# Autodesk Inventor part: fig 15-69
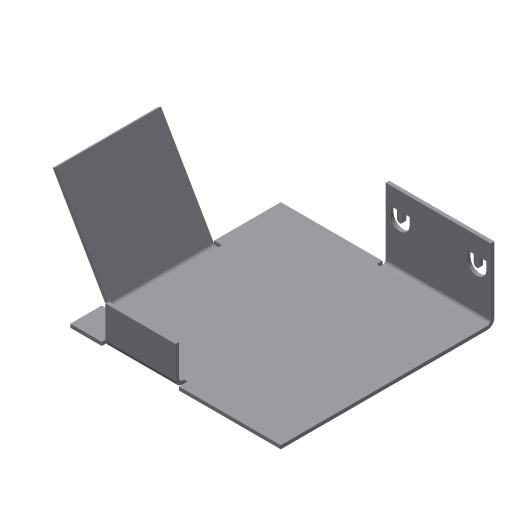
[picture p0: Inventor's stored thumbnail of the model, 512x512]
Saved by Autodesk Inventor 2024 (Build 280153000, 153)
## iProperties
Shininess: 77.0
Angle Display Precision: 2
Document Length Units: 11269
Document Angle Units: 11279
Document Time Units: 11290
Document Mass Units: 11283
Document Length Units Precision: 3
Document Angle Units Precision: 2
Created: 2002-04
Part Number: fig 15-69
Document SubType Name: Sheet Metal
Density: 1 g/cm^3
Sheet Metal Rule: Default
Material: Generic
Appearance: Default
Density: 0.0
Volumn: 0.0
Area: 0.0
PropertySet Name: Model Information
Control State: 0
Master: False
Checked Out: False
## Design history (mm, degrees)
node "Face1"
  sketch "Sketch1"
    geometry: L1 (12.647, 25.882)-(12.647, -14.118); L2 (12.647, -14.118)-(-17.353, -14.118); L3 (-17.353, -14.118)-(-17.353, 15.882); L4 (-17.353, 15.882)-(-2.353, 15.882); L5 (-2.353, 15.882)-(-2.353, 25.882); L6 (-2.353, 25.882)-(12.647, 25.882); 1 further point
    constraints: 12 end point, 4 parallel, 1 perpendicular
    dimensions: "d5" = 30 distance of L2.end L3.end; "d6" = 10 distance of L4.end L5.end; "d7" = 15 distance of L3.end L4.end; "d25" = 15 distance of L5.end L1.start
sketch "Sketch3"
  geometry: L1 (10, -15)-(10, 0)
  constraints: 2 end point
feature "Fold3" sketch "Sketch3" dims "d26" = 0.5 (= BendRadius), "d27" = 90 deg, "d28" = 0.5 (= BendRadius), "d96" = 0.5 (= BendReliefWidth), "d97" = 0.25 (= BendReliefDepth), "d98" = 1 (= MinimumRemnant), "d107" = 0.5 (= Thickness), "SeamGap" = 0.01
node "Flange2"
sketch "Sketch6"
  geometry: L1 (-6.914, 3.413)-(-5.843, 3.413); L2 (-5.843, 0.624)-(-6.914, 0.624); L3 (-6.914, 2.432)-(-5.843, 2.432); L4 (-5.843, 1.605)-(-6.914, 1.605); L5 (-6.914, 0.624)-(-6.914, 1.605); L6 (-6.914, 2.432)-(-6.914, 3.413); L7 (-6.914, 12.568)-(-6.914, 11.587); L8 (-6.914, 14.376)-(-6.914, 13.395); L9 (-6.914, 11.587)-(-5.843, 11.587); L10 (-5.843, 14.376)-(-6.914, 14.376); L11 (-6.914, 12.568)-(-5.843, 12.568); L12 (-5.843, 13.395)-(-6.914, 13.395); A1 r 1.394 centre (-5.843, 2.018) between (-5.843, 0.624) and (-5.843, 3.413); A2 r 0.413 centre (-5.843, 2.018) between (-5.843, 1.605) and (-5.843, 2.432); A3 r 1.394 centre (-5.843, 12.982) between (-5.843, 11.587) and (-5.843, 14.376); A4 r 0.413 centre (-5.843, 12.982) between (-5.843, 12.568) and (-5.843, 13.395)
  constraints: 24 end point, 8 point on circle, 4 centre point, 3 equal length, 1 perpendicular
cut "Cut1" sketch "Sketch6" dims "d49" = 0.5 (= Thickness), "d50" = 0
node "Flange3"
body "Solid1"
face "Plate1" dims "d107" = 0.5 (= Thickness)
sketch "Sketch5"
  geometry: L1 (20, 0)-(5, 0); L2 (5, 0)-(5, 15); L3 (5, 15)-(20, 15); L4 (20, 15)-(20, 0)
  constraints: 8 end point
face "Plate6" dims "d35" = 10, "d36" = 5, "d38" = 15, "d39" = 60 deg, "d40" = 0.5 (= BendRadius), "d107" = 0.5 (= Thickness), "MinimumRemnant" = 1 (= 2 x Thickness), "BendReliefWidth" = 0.5 (= Thickness)
bend "Bend5" dims "d38" = 15, "d39" = 60 deg, "d40" = 0.5 (= BendRadius), "d99" = 0.5 (= BendReliefWidth), "d100" = 0.25 (= BendReliefDepth), "d101" = 1 (= MinimumRemnant), "d107" = 0.5 (= Thickness), "SeamGap" = 0.01, "MinimumRemnant" = 1 (= 2 x Thickness), "BendReliefWidth" = 0.5 (= Thickness), "TransitionRadius" = 0.5 (= BendRadius)
sketch "Sketch7"
  geometry: L1 (25, 0)-(15, 0); L2 (15, 0)-(15, 5); L3 (15, 5)-(25, 5); L4 (25, 5)-(25, 0)
  constraints: 8 end point
face "Plate7" dims "d57" = 5, "d58" = 10, "d60" = 5, "d61" = 90 deg, "d62" = 0.5 (= BendRadius), "d107" = 0.5 (= Thickness), "MinimumRemnant" = 1 (= 2 x Thickness), "BendReliefWidth" = 0.5 (= Thickness)
bend "Bend7" dims "d59" = 0.5 (= BendRadius), "d60" = 5, "d61" = 90 deg, "d62" = 0.5 (= BendRadius), "d102" = 0.5 (= BendReliefWidth), "d103" = 0.25 (= BendReliefDepth), "d104" = 1 (= MinimumRemnant), "d107" = 0.5 (= Thickness), "SeamGap" = 0.01, "MinimumRemnant" = 1 (= 2 x Thickness), "BendReliefWidth" = 0.5 (= Thickness)
other parameters: "Thickness" = 0.5, "BendRadius" = 0.5 (= Thickness), "BendReliefDepth" = 0.25 (= 0.5 x Thickness), "CornerReliefSize" = 2 (= 4 x Thickness), "d0" = 0.5 (= BendRadius), "d13" = 0.5 (= BendRadius), "d31" = 0.5 (= BendRadius), "d37" = 0.5 (= BendRadius), "JacobiRadiusSize" = 0.5 (= Thickness), "GapSize" = 0.5 (= Thickness)
